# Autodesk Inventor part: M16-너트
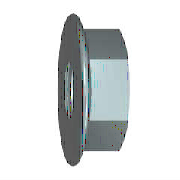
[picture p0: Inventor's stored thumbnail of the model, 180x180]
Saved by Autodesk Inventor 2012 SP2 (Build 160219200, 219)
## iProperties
IsCustomPart: 0
Company: 한국ATC센터
Created: 2009-02
Part Number: M16-너트
Material: Steel, Mild
Description: 플랜지붙이 6각 너트
Document SubType Name: Modeling
Standard: JIS B 1190
Designer: KYOUNG IL JANG
Standards Organization: JIS
Language: ko-KR
Size Designation: M 16
Categories: <MemberInstance><Categories><Category DisplayName="조임쇠" InternalName="e4da775c-781d-43d5-af7c-5136215cf5a6" Mnemonic="FSTN"><Category DisplayName="너트" InternalN
Density: 1 g/cm^3
Author: KYOUNG IL JANG
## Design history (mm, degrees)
workaxis "Work Axis1"
workplane "Work Plane1"
revolve "링" stored, may be unused: angle "d8" = 90 deg
sketch "스케치2"
  geometry: L1 (-11, -6.351)-(-11, 6.351); L2 (-11, 6.351)-(0, 12.702); L3 (0, 12.702)-(11, 6.351); L4 (11, 6.351)-(11, -6.351); L5 (11, -6.351)-(0, -12.702); L6 (0, -12.702)-(-11, -6.351); C1 r 4.9 at (0, 0); C2 r 14.7 at (0, 0) reference; 1 further point
  constraints: 12 end point, 1 centre point, 1 coincident, 1 vertical, 11 other
  dimensions: "d6" = 25.40341 distance of L5.end L2.end (= 1.1547 x SW)
extrude "본체" join sketch "스케치2" distance "d7" = 15 (= KOH); taper "d9" = 0 deg
revolve "모따기1" stored, may be unused: angle "d24" = 90 deg
sketch "스케치4"
  geometry: C1 r 14.7 at (0, 0) reference; 1 further point
  constraints: 1 coincident
hole "스레드" sketch "스케치4" diameter "d25" = 13.835; stored, may be unused: countersink angle "d29" = 82 deg, drill point angle "d31" = 118 deg; dims "d26" = 6, "d27" = 4, "d28" = 2, "d30" = 8
body "Solid1"
chamfer "모따기2" distance "d12" = 1.08253 (= -0.5 x GD1 + 0.5 x NND); stored, may be unused: angle "d13" = 30 deg, second distance "d46" = 1.08253 (= -0.5 x GD1 + 0.5 x NND)
chamfer "모따기3" distance "d51" = 1.08253 (= -0.5 x GD1 + 0.5 x NND); stored, may be unused: second distance "d52" = 2, angle "d53" = 45 deg
sketch "스케치1"
  geometry: L1 (-3.414, 0)-(18.069, 0) reference; L2 (6.015, 11)-(3.359, 15.6); L3 (6.015, 11)-(15, 11); L4 (15, 11)-(15, 0); L5 (6.015, 11)-(6.015, 0); L6 (0, -3.378)-(0, 20.266) reference; A1 r 1.8 centre (1.8, 14.7) between (3.359, 15.6) and (0, 14.7); 1 further point
  constraints: 8 end point, 3 point on line, 2 perpendicular, 2 point on circle, 2 tangent, 1 centre point, 1 parallel
  dimensions: "d2" = 22 diameter of L3 L1 (= SW); "d4" = 33 dimension on A1 L1 (= LADI); "d5" = 1.8 radius of A1 (= PHH); "d15" = 15 distance between parallel lines of L4 L6 (= KOH); "d16" = 30 deg angle of L6 L2 (= KEWI)
sketch "스케치3"
  geometry: L1 (5.032, 12.702)-(15, 12.702) reference; L2 (15, 6.351)-(15, 12.702) reference; L3 (0, -14.7)-(0, 14.7) reference; L4 (-3, 0)-(18, 0) reference; L5 (14.018, 12.702)-(15, 11)
  constraints: 2 end point, 2 point on line
  dimensions: "d10" = 30 deg angle of L2 L5 (= ANG1); "d11" = 22 diameter of L5.end L4 (= SW0)
other parameters: "ANG1" = 30 deg [user parameter; used in 1 equation term], "KEWI" = 30 deg [user parameter; used in 1 equation term], "NND" = 16 [user parameter; used in 3 equation terms], "LADI" = 33 [user parameter; used in 2 equation terms], "SW" = 22 [user parameter; used in 4 equation terms], "PHH" = 1.8 [user parameter; used in 2 equation terms], "KOH" = 15 [user parameter; used in 2 equation terms], "SW0" = 22 (= SW) [user parameter; used in 1 equation term], "GD1" = 13.83494 (computed from THREADDIA, PTC, TOA) [user parameter; used in 3 equation terms], "d1" = 33 (= LADI), "d3" = 1.8 (= PHH), "d45" = 0, "d47" = 0, "d49" = 0, "d54" = 0, "GUL" = 1.08253 (= 0.541266 x PTC) [user parameter], "TPU" = 5 (computed from PTC) [user parameter], "RR" = 2 [user parameter], "THREADDIA" = 16 [user parameter; used in 1 equation term], "TOA" = 30 deg [user parameter; used in 1 equation term], "PTC" = 2 [user parameter; used in 4 equation terms], "GAL" = 1.08253 (= 0.541266 x PTC) [user parameter], "E0" = 25.41 (= 1.155 x SW) [user parameter]
